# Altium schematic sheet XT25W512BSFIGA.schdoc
size 127 x 101 mm
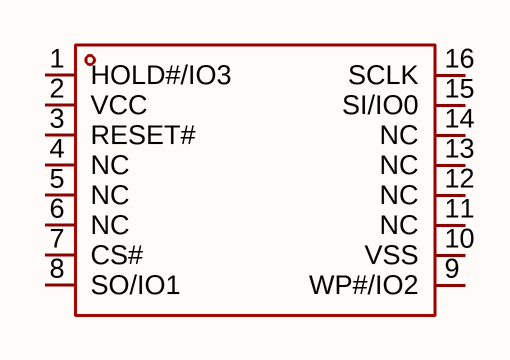
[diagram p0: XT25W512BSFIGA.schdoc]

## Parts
U?  xt25w512bsfiga  [SOP-16_L10.3-W7.5-P1.27-LS10.3-BL]  (value not drawn)

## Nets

Not connected (* = marked no-connect by the designer): U? 1(HOLD#/IO3) 2(VCC) 3(RESET#) 4(NC) 5(NC) 6(NC) 7(CS#) 8(SO/IO1) 9(WP#/IO2) 10(VSS) 11(NC) 12(NC) 13(NC) 14(NC) 15(SI/IO0) 16(SCLK)

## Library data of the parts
U? = xt25w512bsfiga: 接口类型:SPI;存储容量:512Mbit;时钟频率(fc):70MHz;; Manufacturer: XTX(芯天下); AddInBom: yes; ModelId: 89cbb1eeec7e4dc89e56d8a524192cc7; ModelTransform: 405.511,405.511,0,0,0,0,0,0,0; Interface: SPI; Clock Frequency: 70MHz; Voltage - Supply: 1.65V~3.6V; Standby Supply Current: 1uA; Program / Erase Cycles: 100000次; Page Programming Time (Tpp): 300us; Block Erase Time(tBE): 520ms@(64KB); Data Retention - TDR (Year): 20年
